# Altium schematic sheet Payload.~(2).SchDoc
size 381 x 241 mm; SheetNumber: 1; SheetTotal: 1
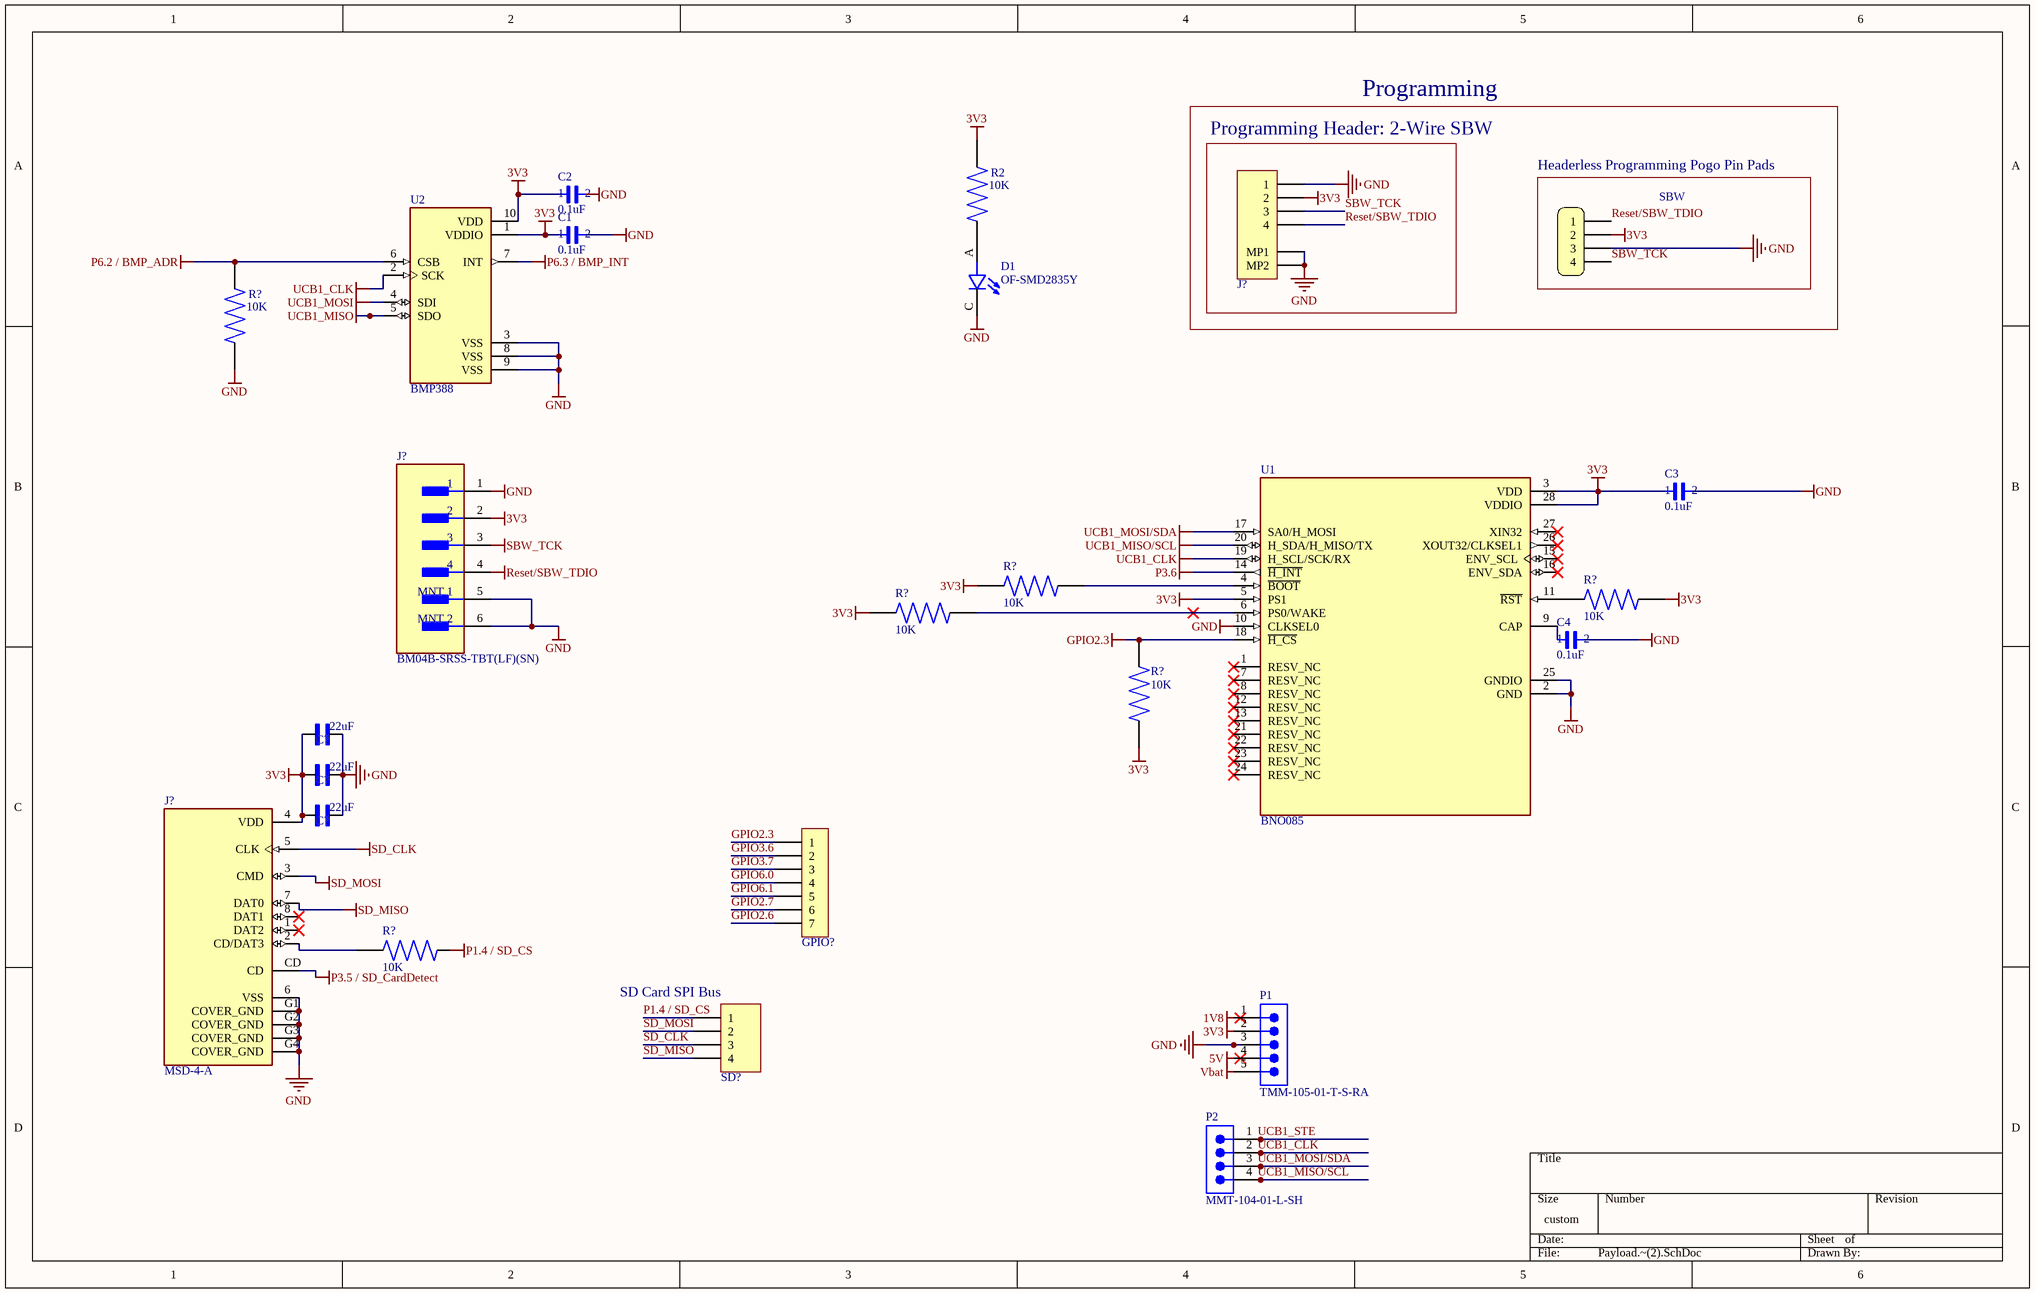
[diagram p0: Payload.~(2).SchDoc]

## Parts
(Parts that share a designator on the sheet are numbered #1, #2 ... from top to bottom, then left to right.)
C1  0.1uF  [0603]
C2  0.1uF  [0603]
C3  0.1uF  [0603]
C4  0.1uF  [0603]
C?#1  22uF  [CAPC2012X94N]
C?#2  22uF  [CAPC2012X94N]
C?#3  22uF  [CAPC2012X94N]
D1  OF-SMD2835Y  [LED_OF-SMD2835Y]
GPIO?  HDR,2.54mm,1x7  [HEADER_2.54MM_1x7PIN]  (value not drawn)  (no BOM)
J?#1  5015680407  [MOLEX_5015680407]  (value not drawn)
J?#2  BM04B-SRSS-TBT(LF)(SN)  [FP-BM04B-SRSS-TBT_LF_SN-MFG]
J?#3  MSD-4-A  [CUI_MSD-4-A]
P1  TMM-105-01-T-S-RA  [SMTC-TMM-105-01-X-S-RA]
P2  MMT-104-01-L-SH  [SMTC-MMT-104-01-X-SH]
PP?  Headerless Pogo Holes 4-pin  [POGO_4_PIN_HEADER]  (value not drawn)  (no BOM)
R2  10K  [RESC1607X60N]
R?#1  10K  [RESC1607X60N]
R?#2  10K  [RESC1607X60N]
R?#3  10K  [RESC1607X60N]
R?#4  10K  [RESC1607X60N]
R?#5  10K  [RESC1607X60N]
R?#6  10K  [RESC1607X60N]
SD?  Header 4  [HDR1X4]  (value not drawn)  (no BOM)
U1  BNO085  [IC_BNO085]
U2  BMP388  [PQFN50P200X200X80-10N]

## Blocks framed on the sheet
Programming Header: 2-Wire SBW: J?#1
Headerless Programming Pogo Pin Pads: PP?

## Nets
3V3: C1.1 C2.1 C3.1 C?#1.1 C?#2.1 C?#3.1 J?#1.2 J?#2.2 J?#3.4(VDD) PP?.2 R2.2 R?#2.2 R?#3.2 R?#4.2 R?#5.2 U1.3(VDD) U1.5(PS1) U1.28(VDDIO) U2.1(VDDIO) U2.10(VDD)
GND: C1.2 C2.2 C3.2 C4.2 C?#1.2 C?#2.2 C?#3.2 D1.C J?#1.1 J?#1.MP1 J?#1.MP2 J?#2.1 J?#2.5(MNT_1) J?#2.6(MNT_2) J?#3.6(VSS) J?#3.G1(COVER_GND) J?#3.G2(COVER_GND) J?#3.G3(COVER_GND) J?#3.G4(COVER_GND) P1.3 PP?.3 R?#1.1 U1.2(GND) U1.10(CLKSEL0) U1.25(GNDIO) U2.3(VSS) U2.8(VSS) U2.9(VSS)
GPIO2.3: GPIO?.1 R?#5.1 U1.18(~{H_CS})
P1.4 / SD_CS: SD?.1
P3.5 / SD_CardDetect: J?#3.CD
P3.6: U1.14(~{H_INT})
P6.2 / BMP_ADR: R?#1.2 U2.6(CSB)
P6.3 / BMP_INT: U2.7(INT)
Reset/SBW_TDIO: J?#1.4 J?#2.4 PP?.1
SBW_TCK: J?#1.3 J?#2.3 PP?.4
SD_CLK: J?#3.5(CLK) SD?.3
SD_MISO: J?#3.7(DAT0) SD?.4
SD_MOSI: J?#3.3(CMD) SD?.2
UCB1_CLK: P2.2 U1.19(H_SCL/SCK/RX) U2.2(SCK)
UCB1_MISO: U2.5(SDO)
UCB1_MISO/SCL: P2.4 U1.20(H_SDA/H_MISO/TX)
UCB1_MOSI: U2.4(SDI)
UCB1_MOSI/SDA: P2.3 U1.17(SA0/H_MOSI)
GPIO2.6: GPIO?.7
GPIO2.7: GPIO?.6
GPIO3.6: GPIO?.2
GPIO3.7: GPIO?.3
GPIO6.0: GPIO?.4
GPIO6.1: GPIO?.5
UCB1_STE: P2.1
NetC4_1: C4.1 U1.9(CAP)
NetD1_A: D1.A R2.1
NetJ?#3_2: J?#3.2(CD/DAT3) R?#6.2
NetR?#2_1: R?#2.1 U1.4(~{BOOT})
NetR?#3_1: R?#3.1 U1.11(~{RST})
NetR?#4_1: R?#4.1 U1.6(PS0/WAKE)

Not connected (* = marked no-connect by the designer): J?#3 1(DAT2)* 8(DAT1)*; P1 1 2 4 5; R?#6 1; U1 1(RESV_NC)* 7(RESV_NC)* 8(RESV_NC)* 12(RESV_NC)* 13(RESV_NC)* 15(ENV_SCL)* 16(ENV_SDA)* 21(RESV_NC)* 22(RESV_NC)* 23(RESV_NC)* 24(RESV_NC)* 26(XOUT32/CLKSEL1)* 27(XIN32)*

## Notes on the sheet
- Programming
- SBW
- (near SD?) SD Card SPI Bus
- Labels drawn without touching a wire or pin: 1V8, 3V3, 5V, P1.4 / SD_CS, Vbat

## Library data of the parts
C1-C4 = C0603: 0 Ohms Jumper 0.1W, 1/10W Chip Resistor 0603 (1608 Metric) Moisture Resistant Thick Film; MF: Yageo
C?#1-C?#3 = 0805YC103J4T2A: 10000 pF Â±5% 16V Ceramic Capacitor X7R 0805 (2012 Metric); MF: AVX
D1 = OF-SMD2835Y: LED; SMD; 2835, PLCC2; yellow; 2200-2800mcd; 2.8x3.5x0.75mm; 120Â°
GPIO? = HDR,2.54mm,1x7: Connector - 2.54mm, 1x7-pin
J?#1 = 5015680407: Connector - Picoclasp  04-pin, SMT, RA; APSS Standard Part: APSS Standard; Pitch: 1mm
J?#2 = CMP-17439-000370-1: CONN HEADER SMD 4POS 1MM; Voltage Rating: 50V; Number of Positions: 4; Pitch: 0.039inch; Mated Stacking Heights: 4.9mm
J?#3 = MSD-4-A: Micro SD Card Connector, 9 Positions, Connector and Ejector, Push In, Auto Eject Out, Surface Mount, 1.8 mm Height Above Board, Gold Flash; MF: Same Sky
P1 = CMP-1029-00184-1: Low Profile Through-Hole Header, Right Angle, -55 to 105 degC, 2 mm Pitch, 5-Pin, Male, RoHS; Manufacturer: Samtec; Pitch: 2 mm
P2 = CMP-1029-00050-1: Horizontal Surface Mount Header, -55 to 125 degC, 2 mm Pitch, 4-Pin, Male, RoHS; Manufacturer: Samtec; Pitch: 2 mm
R2 R?#1-R?#6 = RC0603JR-070RL: 0 Ohms Jumper 0.1W, 1/10W Chip Resistor 0603 (1608 Metric) Moisture Resistant Thick Film; MF: Yageo
SD? = Header 4: Header, 4-Pin
U1 = BNO085: Accelerometer, Gyroscope, Magnetometer, 9 Axis Sensor IÂ²C, SPI, UART Output; MF: Hillcrest Laboratories,
U2 = BMP388: P-Sensor SPI I2C 1, 25 Bar SMD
